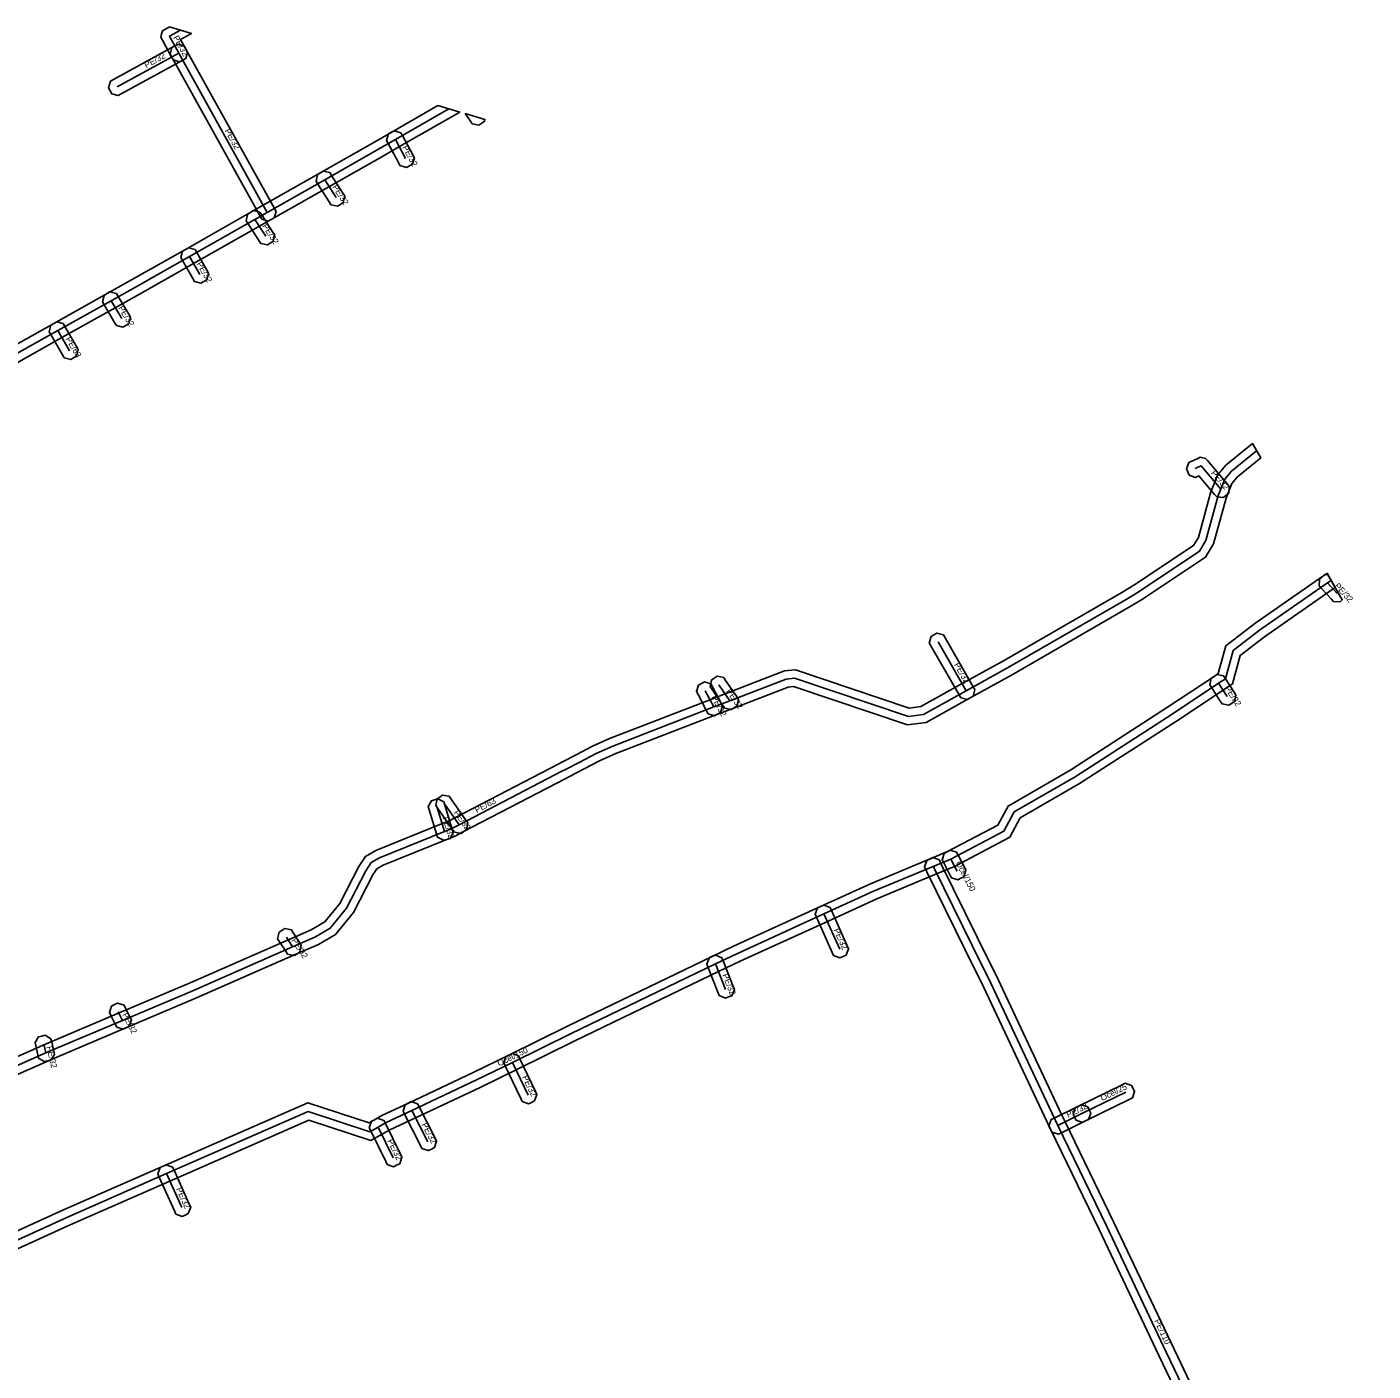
# Model space of a CAD drawing. Extents: x -574390 to -573768, y -1190959 to -1190603.
# Drawn here: x -573979.8 to -573815, y -1190794.4 to -1190629.9 of the extents above; entities that cross this region are included whole.
import ezdxf

# ---------------------------------------------------------------- set-up
doc = ezdxf.new("R2010")
doc.units = 0
for name, color, linetype in [('1', 7, 'Continuous'), ('24', 7, 'Continuous'), ('28', 7, 'Continuous'), ('30', 7, 'Continuous')]:
    doc.layers.add(name, color=color, linetype=linetype)

msp = doc.modelspace()

# ---------------------------------------------------------------- linework, layer by layer
at = {"layer": '1'}
for points in [[(-573962.341, -1190629.914), (-573959.639, -1190630.706), (-573960.97, -1190631.442), (-573960.315, -1190632.626), (-573960.115, -1190632.988), (-573960.344, -1190633.785), (-573960.706, -1190633.985), (-573961.068, -1190634.185), (-573961.865, -1190633.956), (-573962.065, -1190633.594), (-573963.205, -1190631.534), (-573963.406, -1190631.172), (-573963.291, -1190630.773), (-573963.176, -1190630.375), (-573962.813, -1190630.175)], [(-573969.564, -1190636.562), (-573969.201, -1190636.363), (-573961.671, -1190632.233), (-573961.308, -1190632.034), (-573960.512, -1190632.266), (-573960.313, -1190632.629), (-573960.114, -1190632.992), (-573960.346, -1190633.788), (-573960.709, -1190633.987), (-573968.239, -1190638.117), (-573968.602, -1190638.316), (-573969.398, -1190638.084), (-573969.597, -1190637.721), (-573969.796, -1190637.358)], [(-573951.043, -1190653.447), (-573951.244, -1190653.085), (-573962.064, -1190633.595), (-573962.265, -1190633.233), (-573962.037, -1190632.437), (-573961.675, -1190632.236), (-573961.313, -1190632.035), (-573960.517, -1190632.263), (-573960.316, -1190632.625), (-573949.496, -1190652.115), (-573949.295, -1190652.477), (-573949.523, -1190653.273), (-573949.885, -1190653.474), (-573950.247, -1190653.675)], [(-573925.513, -1190641.437), (-573926.145, -1190640.52), (-573923.739, -1190641.225), (-573923.782, -1190641.458), (-573924.123, -1190641.693), (-573924.464, -1190641.928), (-573925.278, -1190641.778)], [(-573934.005, -1190642.852), (-573933.809, -1190643.217), (-573932.559, -1190645.547), (-573932.363, -1190645.912), (-573932.602, -1190646.705), (-573932.967, -1190646.901), (-573933.332, -1190647.097), (-573934.125, -1190646.858), (-573934.321, -1190646.493), (-573935.571, -1190644.163), (-573935.767, -1190643.798), (-573935.528, -1190643.005), (-573935.163, -1190642.809), (-573934.798, -1190642.613)], [(-573942.708, -1190647.724), (-573942.486, -1190648.073), (-573941.106, -1190650.243), (-573940.884, -1190650.593), (-573941.064, -1190651.402), (-573941.413, -1190651.624), (-573941.763, -1190651.846), (-573942.572, -1190651.666), (-573942.794, -1190651.317), (-573944.174, -1190649.147), (-573944.396, -1190648.797), (-573944.216, -1190647.988), (-573943.867, -1190647.766), (-573943.517, -1190647.544)], [(-573951.265, -1190652.57), (-573951.04, -1190652.918), (-573949.71, -1190654.978), (-573949.485, -1190655.326), (-573949.66, -1190656.135), (-573950.008, -1190656.36), (-573950.356, -1190656.585), (-573951.165, -1190656.41), (-573951.39, -1190656.062), (-573952.72, -1190654.002), (-573952.945, -1190653.654), (-573952.77, -1190652.845), (-573952.422, -1190652.62), (-573952.074, -1190652.395)], [(-573959.207, -1190657.144), (-573959.002, -1190657.504), (-573957.752, -1190659.694), (-573957.547, -1190660.054), (-573957.764, -1190660.853), (-573958.124, -1190661.058), (-573958.484, -1190661.263), (-573959.283, -1190661.046), (-573959.488, -1190660.686), (-573960.738, -1190658.496), (-573960.943, -1190658.136), (-573960.726, -1190657.337), (-573960.366, -1190657.132), (-573960.006, -1190656.927)], [(-573968.822, -1190662.543), (-573968.61, -1190662.899), (-573967.32, -1190665.069), (-573967.108, -1190665.425), (-573967.313, -1190666.228), (-573967.669, -1190666.44), (-573968.025, -1190666.652), (-573968.828, -1190666.447), (-573969.04, -1190666.091), (-573970.33, -1190663.921), (-573970.542, -1190663.565), (-573970.337, -1190662.762), (-573969.981, -1190662.55), (-573969.625, -1190662.338)], [(-573975.333, -1190666.201), (-573975.125, -1190666.559), (-573973.695, -1190669.029), (-573973.487, -1190669.387), (-573973.701, -1190670.187), (-573974.059, -1190670.395), (-573974.417, -1190670.603), (-573975.217, -1190670.389), (-573975.425, -1190670.031), (-573976.855, -1190667.561), (-573977.063, -1190667.203), (-573976.849, -1190666.403), (-573976.491, -1190666.195), (-573976.133, -1190665.987)], [(-573834.164, -1190687.423), (-573834.432, -1190687.107), (-573836.352, -1190684.845), (-573836.383, -1190684.859), (-573836.76, -1190685.032), (-573837.536, -1190684.744), (-573837.709, -1190684.367), (-573837.882, -1190683.99), (-573837.594, -1190683.214), (-573837.217, -1190683.041), (-573836.497, -1190682.711), (-573836.191, -1190682.571), (-573835.535, -1190682.717), (-573835.318, -1190682.973), (-573832.908, -1190685.813), (-573832.64, -1190686.129), (-573832.707, -1190686.954), (-573833.023, -1190687.222), (-573833.339, -1190687.49)], [(-573820.566, -1190696.941), (-573818.803, -1190700.002), (-573819.056, -1190700.236), (-573819.884, -1190700.202), (-573820.165, -1190699.898), (-573821.345, -1190698.618), (-573821.626, -1190698.314), (-573821.592, -1190697.486), (-573821.288, -1190697.205), (-573820.984, -1190696.924)], [(-573865.49, -1190711.998), (-573865.697, -1190711.639), (-573869.147, -1190705.649), (-573869.354, -1190705.29), (-573869.138, -1190704.49), (-573868.779, -1190704.283), (-573868.42, -1190704.076), (-573867.62, -1190704.292), (-573867.413, -1190704.651), (-573863.963, -1190710.641), (-573863.756, -1190711), (-573863.972, -1190711.8), (-573864.331, -1190712.007), (-573864.69, -1190712.214)], [(-573894.361, -1190713.277), (-573894.595, -1190712.935), (-573895.925, -1190710.995), (-573896.159, -1190710.654), (-573896.007, -1190709.839), (-573895.665, -1190709.605), (-573895.324, -1190709.371), (-573894.509, -1190709.523), (-573894.275, -1190709.865), (-573892.945, -1190711.805), (-573892.711, -1190712.146), (-573892.863, -1190712.961), (-573893.205, -1190713.195), (-573893.546, -1190713.429)], [(-573833.334, -1190709.33), (-573833.109, -1190709.678), (-573832.059, -1190711.308), (-573831.835, -1190711.656), (-573832.01, -1190712.466), (-573832.358, -1190712.691), (-573832.706, -1190712.915), (-573833.516, -1190712.74), (-573833.741, -1190712.392), (-573834.791, -1190710.762), (-573835.015, -1190710.414), (-573834.84, -1190709.604), (-573834.492, -1190709.379), (-573834.144, -1190709.155)], [(-573896.412, -1190713.952), (-573896.605, -1190713.585), (-573897.645, -1190711.605), (-573897.838, -1190711.238), (-573897.592, -1190710.448), (-573897.225, -1190710.255), (-573896.858, -1190710.062), (-573896.068, -1190710.308), (-573895.875, -1190710.675), (-573894.835, -1190712.655), (-573894.642, -1190713.022), (-573894.888, -1190713.812), (-573895.255, -1190714.005), (-573895.622, -1190714.198)], [(-573929.525, -1190729.049), (-573929.646, -1190728.653), (-573930.546, -1190725.713), (-573930.667, -1190725.317), (-573930.279, -1190724.585), (-573929.883, -1190724.464), (-573929.487, -1190724.343), (-573928.755, -1190724.731), (-573928.634, -1190725.127), (-573927.734, -1190728.067), (-573927.613, -1190728.463), (-573928.001, -1190729.195), (-573928.397, -1190729.316), (-573928.793, -1190729.437)], [(-573927.464, -1190728.442), (-573927.701, -1190728.102), (-573929.491, -1190725.532), (-573929.728, -1190725.192), (-573929.582, -1190724.376), (-573929.242, -1190724.139), (-573928.902, -1190723.902), (-573928.086, -1190724.048), (-573927.849, -1190724.388), (-573926.059, -1190726.958), (-573925.822, -1190727.298), (-573925.968, -1190728.114), (-573926.308, -1190728.351), (-573926.648, -1190728.588)], [(-573866.637, -1190734.022), (-573866.828, -1190733.655), (-573867.588, -1190732.191), (-573867.779, -1190731.823), (-573867.528, -1190731.033), (-573867.161, -1190730.842), (-573866.793, -1190730.651), (-573866.003, -1190730.902), (-573865.812, -1190731.269), (-573865.052, -1190732.733), (-573864.861, -1190733.101), (-573865.112, -1190733.891), (-573865.479, -1190734.082), (-573865.847, -1190734.273)], [(-573881.054, -1190743.537), (-573881.223, -1190743.159), (-573883.153, -1190738.849), (-573883.322, -1190738.471), (-573883.027, -1190737.696), (-573882.649, -1190737.527), (-573882.271, -1190737.358), (-573881.496, -1190737.653), (-573881.327, -1190738.031), (-573879.397, -1190742.341), (-573879.228, -1190742.719), (-573879.523, -1190743.494), (-573879.901, -1190743.663), (-573880.279, -1190743.832)], [(-573947.883, -1190743.362), (-573948.109, -1190743.015), (-573948.869, -1190741.845), (-573949.094, -1190741.497), (-573948.922, -1190740.687), (-573948.575, -1190740.461), (-573948.227, -1190740.236), (-573947.417, -1190740.408), (-573947.191, -1190740.755), (-573946.431, -1190741.925), (-573946.206, -1190742.273), (-573946.378, -1190743.083), (-573946.725, -1190743.309), (-573947.073, -1190743.534)], [(-573895.06, -1190748.421), (-573895.211, -1190748.035), (-573896.431, -1190744.925), (-573896.582, -1190744.539), (-573896.251, -1190743.78), (-573895.865, -1190743.629), (-573895.479, -1190743.478), (-573894.72, -1190743.809), (-573894.569, -1190744.195), (-573893.349, -1190747.305), (-573893.198, -1190747.691), (-573893.529, -1190748.45), (-573893.915, -1190748.601), (-573894.301, -1190748.752)], [(-573968.789, -1190752.288), (-573968.974, -1190751.917), (-573969.494, -1190750.877), (-573969.68, -1190750.507), (-573969.418, -1190749.721), (-573969.047, -1190749.536), (-573968.677, -1190749.35), (-573967.891, -1190749.612), (-573967.706, -1190749.983), (-573967.186, -1190751.023), (-573967, -1190751.393), (-573967.262, -1190752.179), (-573967.633, -1190752.364), (-573968.003, -1190752.55)], [(-573978.352, -1190756.077), (-573978.445, -1190755.674), (-573978.695, -1190754.584), (-573978.787, -1190754.18), (-573978.347, -1190753.478), (-573977.944, -1190753.385), (-573977.54, -1190753.293), (-573976.838, -1190753.733), (-573976.745, -1190754.136), (-573976.495, -1190755.226), (-573976.403, -1190755.63), (-573976.843, -1190756.332), (-573977.246, -1190756.425), (-573977.65, -1190756.517)], [(-573919.175, -1190761.404), (-573919.353, -1190761.03), (-573921.253, -1190757.04), (-573921.431, -1190756.666), (-573921.154, -1190755.885), (-573920.78, -1190755.707), (-573920.406, -1190755.529), (-573919.625, -1190755.806), (-573919.447, -1190756.18), (-573917.547, -1190760.17), (-573917.369, -1190760.544), (-573917.646, -1190761.325), (-573918.02, -1190761.503), (-573918.394, -1190761.681)], [(-573851.478, -1190762.158), (-573851.106, -1190761.975), (-573845.751, -1190759.343), (-573845.379, -1190759.16), (-573844.596, -1190759.427), (-573844.413, -1190759.799), (-573844.23, -1190760.171), (-573844.497, -1190760.954), (-573844.869, -1190761.137), (-573850.224, -1190763.769), (-573850.596, -1190763.952), (-573851.379, -1190763.685), (-573851.562, -1190763.313), (-573851.745, -1190762.941)], [(-573931.435, -1190767.141), (-573931.622, -1190766.772), (-573933.562, -1190762.942), (-573933.749, -1190762.573), (-573933.491, -1190761.785), (-573933.122, -1190761.598), (-573932.753, -1190761.411), (-573931.965, -1190761.669), (-573931.778, -1190762.038), (-573929.838, -1190765.868), (-573929.651, -1190766.237), (-573929.909, -1190767.025), (-573930.278, -1190767.212), (-573930.647, -1190767.399)], [(-573854.438, -1190763.613), (-573854.066, -1190763.43), (-573851.106, -1190761.975), (-573850.734, -1190761.792), (-573849.951, -1190762.059), (-573849.768, -1190762.431), (-573849.585, -1190762.803), (-573849.852, -1190763.586), (-573850.224, -1190763.769), (-573853.184, -1190765.224), (-573853.556, -1190765.407), (-573854.339, -1190765.14), (-573854.522, -1190764.768), (-573854.705, -1190764.396)], [(-573935.686, -1190769.102), (-573935.868, -1190768.73), (-573937.708, -1190764.97), (-573937.89, -1190764.598), (-573937.622, -1190763.814), (-573937.25, -1190763.632), (-573936.878, -1190763.45), (-573936.094, -1190763.718), (-573935.912, -1190764.09), (-573934.072, -1190767.85), (-573933.89, -1190768.222), (-573934.158, -1190769.006), (-573934.53, -1190769.188), (-573934.902, -1190769.37)], [(-573961.562, -1190775.159), (-573961.732, -1190774.781), (-573963.602, -1190770.631), (-573963.772, -1190770.253), (-573963.479, -1190769.478), (-573963.101, -1190769.308), (-573962.723, -1190769.138), (-573961.948, -1190769.431), (-573961.778, -1190769.809), (-573959.908, -1190773.959), (-573959.738, -1190774.337), (-573960.031, -1190775.112), (-573960.409, -1190775.282), (-573960.787, -1190775.452)]]:
    msp.add_lwpolyline(points, close=True, dxfattribs=at)
for points in [[(-573984.218, -1190670.517), (-573976.478, -1190666.187), (-573969.958, -1190662.537), (-573966.31, -1190660.498), (-573960.363, -1190657.13), (-573952.374, -1190652.591), (-573950.864, -1190651.731), (-573943.823, -1190647.74), (-573937.336, -1190644.062), (-573935.189, -1190642.823), (-573929.473, -1190639.545), (-573926.812, -1190640.324), (-573934.191, -1190644.557), (-573936.344, -1190645.798), (-573942.837, -1190649.48), (-573949.876, -1190653.469), (-573951.386, -1190654.329), (-573959.377, -1190658.87), (-573965.33, -1190662.242), (-573968.982, -1190664.283), (-573975.502, -1190667.933), (-573983.242, -1190672.263)], [(-573994.103, -1190761.685), (-573977.873, -1190754.535), (-573977.206, -1190754.242), (-573968.47, -1190750.549), (-573959.806, -1190746.882), (-573947.671, -1190741.554), (-573945.002, -1190740.386), (-573943.32, -1190739.416), (-573941.502, -1190737.171), (-573939.18, -1190732.647), (-573938.339, -1190731.421), (-573937.064, -1190730.671), (-573929.063, -1190727.432), (-573928.206, -1190727.089), (-573927.34, -1190726.642), (-573914.759, -1190720.106), (-573914.311, -1190719.873), (-573912.581, -1190718.972), (-573910.568, -1190717.93), (-573908.478, -1190716.978), (-573896.08, -1190712.187), (-573894.13, -1190711.437), (-573887.088, -1190708.716), (-573885.71, -1190708.596), (-573871.801, -1190713.259), (-573870.378, -1190713.073), (-573865.315, -1190710.265), (-573860.282, -1190707.479), (-573845.766, -1190699.097), (-573844.314, -1190698.234), (-573837.02, -1190693.361), (-573836.418, -1190692.371), (-573834.93, -1190686.923), (-573834.599, -1190686.09), (-573834.06, -1190684.742), (-573833.056, -1190683.535), (-573829.808, -1190680.9), (-573828.796, -1190682.655), (-573831.644, -1190684.965), (-573832.32, -1190685.778), (-573832.741, -1190686.83), (-573833.03, -1190687.557), (-573834.562, -1190693.169), (-573835.54, -1190694.779), (-573843.246, -1190699.926), (-573844.754, -1190700.823), (-573859.298, -1190709.221), (-573864.345, -1190712.015), (-573869.742, -1190715.007), (-573871.999, -1190715.301), (-573885.95, -1190710.624), (-573886.632, -1190710.684), (-573893.41, -1190713.303), (-573895.36, -1190714.053), (-573907.702, -1190718.822), (-573909.692, -1190719.73), (-573911.659, -1190720.748), (-573913.389, -1190721.647), (-573913.837, -1190721.88), (-573926.42, -1190728.418), (-573927.374, -1190728.911), (-573928.317, -1190729.288), (-573936.176, -1190732.469), (-573936.941, -1190732.919), (-573937.46, -1190733.673), (-573939.818, -1190738.269), (-573942, -1190740.964), (-573944.098, -1190742.174), (-573946.869, -1190743.386), (-573959.014, -1190748.718), (-573967.69, -1190752.391), (-573976.414, -1190756.078), (-573977.067, -1190756.365), (-573993.297, -1190763.515)], [(-573992.903, -1190782.649), (-573975.308, -1190774.667), (-573963.092, -1190769.304), (-573945.391, -1190761.54), (-573937.908, -1190764.002), (-573937.304, -1190763.661), (-573936.362, -1190763.122), (-573933.096, -1190761.585), (-573925.183, -1190757.858), (-573920.79, -1190755.712), (-573913.607, -1190752.191), (-573895.934, -1190743.659), (-573893.324, -1190742.404), (-573882.656, -1190737.53), (-573876.56, -1190734.743), (-573869.239, -1190731.702), (-573867.126, -1190730.824), (-573860.974, -1190727.577), (-573859.704, -1190725.245), (-573852.012, -1190720.797), (-573840.188, -1190713.163), (-573834.503, -1190709.387), (-573833.986, -1190709.044), (-573833.056, -1190705.632), (-573829.51, -1190702.912), (-573821.179, -1190697.118), (-573820.737, -1190696.813), (-573820.669, -1190696.764), (-573819.666, -1190698.504), (-573820.041, -1190698.762), (-573828.33, -1190704.528), (-573831.304, -1190706.808), (-573832.254, -1190710.296), (-573833.397, -1190711.053), (-573839.092, -1190714.837), (-573850.968, -1190722.503), (-573858.216, -1190726.695), (-573859.506, -1190729.063), (-573866.274, -1190732.636), (-573868.471, -1190733.548), (-573875.76, -1190736.577), (-573881.824, -1190739.35), (-573892.476, -1190744.216), (-573895.066, -1190745.461), (-573912.733, -1190753.989), (-573919.91, -1190757.508), (-573924.317, -1190759.662), (-573932.244, -1190763.395), (-573935.438, -1190764.898), (-573936.316, -1190765.399), (-573937.692, -1190766.178), (-573945.289, -1190763.68), (-573962.288, -1190771.136), (-573974.492, -1190776.493), (-573992.077, -1190784.471)], [(-573834.006, -1190807.624), (-573841.203, -1190792.56), (-573848.572, -1190777.053), (-573854.525, -1190764.763), (-573854.932, -1190763.921), (-573863.059, -1190746.658), (-573863.815, -1190745.155), (-573869.638, -1190733.303), (-573869.7, -1190733.175), (-573869.757, -1190733.056), (-573869.936, -1190732.682), (-573869.66, -1190731.902), (-573869.286, -1190731.723), (-573868.912, -1190731.544), (-573868.132, -1190731.82), (-573867.953, -1190732.194), (-573867.9, -1190732.305), (-573867.842, -1190732.423), (-573862.025, -1190744.265), (-573861.261, -1190745.782), (-573853.128, -1190763.059), (-573852.725, -1190763.891), (-573846.768, -1190776.187), (-573839.397, -1190791.7), (-573832.194, -1190806.776)]]:
    msp.add_lwpolyline(points, dxfattribs=at)
at = {"layer": '24'}
for points in [[(-574052.27, -1190712.36), (-574049.75, -1190709.58), (-574045.72, -1190706.98), (-574044.02, -1190705.98), (-574032.12, -1190698.97), (-574018.83, -1190691.28), (-574010.79, -1190686.63), (-574001.67, -1190681.44), (-573999.27, -1190680.08), (-573995.75, -1190678.11), (-573983.73, -1190671.39), (-573975.99, -1190667.06), (-573969.47, -1190663.41), (-573965.82, -1190661.37), (-573959.87, -1190658), (-573951.88, -1190653.46), (-573950.37, -1190652.6), (-573943.33, -1190648.61), (-573936.84, -1190644.93), (-573934.69, -1190643.69), (-573928.142665, -1190639.934461)], [(-573934.69, -1190643.69), (-573933.44, -1190646.02)], [(-573943.33, -1190648.61), (-573941.95, -1190650.78)], [(-573951.88, -1190653.46), (-573950.55, -1190655.52)], [(-573959.87, -1190658), (-573958.62, -1190660.19)], [(-573969.47, -1190663.41), (-573968.18, -1190665.58)], [(-573993.7, -1190762.6), (-573977.47, -1190755.45), (-573976.81, -1190755.16), (-573968.08, -1190751.47), (-573959.41, -1190747.8), (-573947.27, -1190742.47), (-573944.55, -1190741.28), (-573942.66, -1190740.19), (-573940.66, -1190737.72), (-573938.32, -1190733.16), (-573937.64, -1190732.17), (-573936.62, -1190731.57), (-573928.69, -1190728.36), (-573927.79, -1190728), (-573926.88, -1190727.53), (-573914.298, -1190720.993), (-573913.85, -1190720.76), (-573912.12, -1190719.86), (-573910.13, -1190718.83), (-573908.09, -1190717.9), (-573895.72, -1190713.12), (-573893.77, -1190712.37), (-573886.86, -1190709.7), (-573885.83, -1190709.61), (-573871.9, -1190714.28), (-573870.06, -1190714.04), (-573864.83, -1190711.14), (-573859.79, -1190708.35), (-573845.26, -1190699.96), (-573843.78, -1190699.08), (-573836.28, -1190694.07), (-573835.49, -1190692.77), (-573833.98, -1190687.24), (-573833.67, -1190686.46), (-573833.19, -1190685.26), (-573832.35, -1190684.25), (-573829.30194, -1190681.77754)], [(-573820.16685, -1190697.634719), (-573820.61, -1190697.94), (-573828.92, -1190703.72), (-573832.18, -1190706.22), (-573833.12, -1190709.67), (-573833.95, -1190710.22), (-573839.64, -1190714), (-573851.49, -1190721.65), (-573858.96, -1190725.97), (-573860.24, -1190728.32), (-573866.7, -1190731.73), (-573868.855, -1190732.625), (-573876.16, -1190735.66), (-573882.24, -1190738.44), (-573892.9, -1190743.31), (-573895.5, -1190744.56), (-573913.17, -1190753.09), (-573920.35, -1190756.61), (-573924.75, -1190758.76), (-573932.67, -1190762.49), (-573935.9, -1190764.01), (-573936.81, -1190764.53), (-573937.8, -1190765.09), (-573945.34, -1190762.61), (-573962.69, -1190770.22), (-573974.9, -1190775.58), (-573992.49, -1190783.56)], [(-573833.95, -1190710.22), (-573832.9, -1190711.85)], [(-573868.855, -1190732.625), (-573868.8, -1190732.74), (-573868.74, -1190732.863), (-573862.92, -1190744.71), (-573862.16, -1190746.22), (-573854.03, -1190763.49), (-573853.625, -1190764.327), (-573847.67, -1190776.62), (-573840.3, -1190792.13), (-573833.1, -1190807.2), (-573829.825, -1190814.346), (-573827.6, -1190819.2), (-573824.15, -1190827.92), (-573824.07, -1190828.1), (-573818.76, -1190838.89), (-573818.159, -1190840.111), (-573816.96, -1190842.55), (-573815.04, -1190841.61)], [(-573865.94, -1190733.194), (-573866.7, -1190731.73)], [(-573853.625, -1190764.327), (-573850.665, -1190762.872)]]:
    msp.add_lwpolyline(points, dxfattribs=at)
at = {"layer": '28'}
for points in [[(-573961.19, -1190633.11), (-573962.33, -1190631.05), (-573960.990398, -1190630.310287)], [(-573968.72, -1190637.24), (-573961.19, -1190633.11)], [(-573950.37, -1190652.6), (-573961.19, -1190633.11)], [(-573975.99, -1190667.06), (-573974.56, -1190669.53)], [(-573833.67, -1190686.46), (-573836.08, -1190683.62), (-573836.8, -1190683.95)], [(-573819.43, -1190699.22), (-573820.61, -1190697.94)], [(-573864.83, -1190711.14), (-573868.28, -1190705.15)], [(-573895.72, -1190713.12), (-573896.76, -1190711.14)], [(-573893.77, -1190712.37), (-573895.1, -1190710.43)], [(-573928.69, -1190728.36), (-573929.59, -1190725.42)], [(-573926.88, -1190727.53), (-573928.67, -1190724.96)], [(-573880.31, -1190742.75), (-573882.24, -1190738.44)], [(-573947.27, -1190742.47), (-573948.03, -1190741.3)], [(-573894.28, -1190747.67), (-573895.5, -1190744.56)], [(-573968.08, -1190751.47), (-573968.6, -1190750.43)], [(-573977.47, -1190755.45), (-573977.72, -1190754.36)], [(-573918.45, -1190760.6), (-573920.35, -1190756.61)], [(-573850.665, -1190762.872), (-573845.31, -1190760.24)], [(-573930.73, -1190766.32), (-573932.67, -1190762.49)], [(-573934.97, -1190768.29), (-573936.81, -1190764.53)], [(-573960.82, -1190774.37), (-573962.69, -1190770.22)]]:
    msp.add_lwpolyline(points, dxfattribs=at)

# ---------------------------------------------------------------- texts
at = {"layer": '30'}
for s, rotation, p in [('PE/32', 298.96005669, (-573961.930477, -1190631.210542)), ('PE/32', 28.74356922, (-573965.155, -1190634.975)), ('PE/32', 299.03712902, (-573955.604269, -1190642.611285)), ('PE/32', 298.2126988, (-573933.865, -1190644.655)), ('PE/32', 302.45410438, (-573942.44, -1190649.495)), ('PE/32', 302.84754327, (-573951.015, -1190654.29)), ('PE/32', 299.71669843, (-573959.045, -1190658.895)), ('PE/32', 300.73021525, (-573968.625, -1190664.295)), ('PE/63', 300.06858282, (-573975.075, -1190668.095)), ('PE/32', 310.31765449, (-573834.931229, -1190684.538054)), ('PE/32', 312.67218491, (-573819.82, -1190698.38)), ('PE/32', 299.94021874, (-573866.355, -1190707.945)), ('PE/32', 304.4332494, (-573894.235, -1190711.2)), ('PE/32', 302.78849162, (-573833.225, -1190710.835)), ('PE/32', 297.71081402, (-573896.04, -1190711.93)), ('PE/63', 27.45421116, (-573924.730404, -1190726.109263)), ('PE/32', 304.85713632, (-573927.575, -1190726.045)), ('PE/32', 287.02052561, (-573928.94, -1190726.69)), ('Ocel/150', 297.43498531, (-573866.143037, -1190732.217623)), ('PE/32', 294.12263587, (-573881.075, -1190740.395)), ('PE/32', 303.00665128, (-573947.45, -1190741.685)), ('PE/32', 291.41923097, (-573894.69, -1190745.915)), ('PE/32', 296.56505118, (-573968.14, -1190750.75)), ('PE/32', 282.91781284, (-573977.395, -1190754.705)), ('Ocel/150', 26.04181659, (-573921.985919, -1190757.111642)), ('PE/32', 295.46334506, (-573919.2, -1190758.405)), ('Ocel/25', 26.17426755, (-573848.1875, -1190761.356)), ('PE/32', 26.17661117, (-573852.345, -1190763.3995)), ('PE/32', 296.863464, (-573931.5, -1190764.205)), ('PE/32', 296.07535558, (-573935.69, -1190766.21)), ('PE/32', 294.25644199, (-573961.555, -1190772.095)), ('PE/110', 295.41600623, (-573841.856333, -1190788.233837))]:
    msp.add_text(s, height=0.75, rotation=rotation, dxfattribs=at).set_placement(p)

doc.saveas('drawing.dxf')
